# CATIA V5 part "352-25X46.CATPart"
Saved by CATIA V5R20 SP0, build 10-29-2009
Part number: 352-25X46
Definition: NONE
Nomenclature: 352-25X46
Source: Unknown
Description: 352-25X46
Bounding box of the stored display mesh (mm): x 0 to 46, y -17 to 17, z -17 to 17
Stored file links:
  C:\Users\Utente\Desktop\IO LAVORO\3D X SITO CF\X SITO\PLASTICA\352\352-25X46.CATPart

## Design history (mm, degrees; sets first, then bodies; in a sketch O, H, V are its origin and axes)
Body1 "352-25X46" (main body)
  Solid1: solid without history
